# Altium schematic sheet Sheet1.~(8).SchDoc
size A
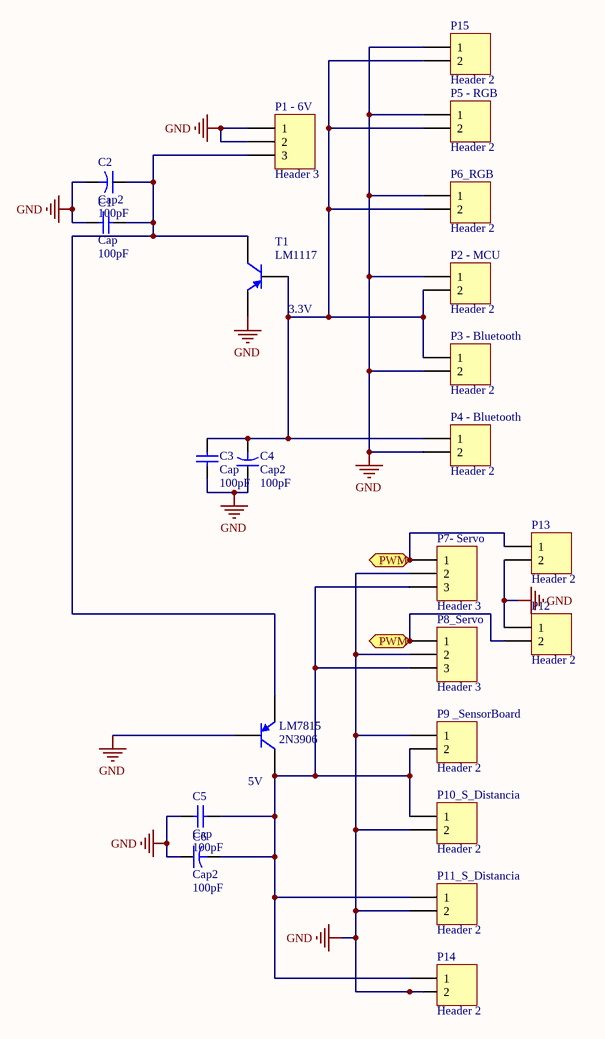
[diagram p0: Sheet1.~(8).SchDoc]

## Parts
C1  Cap  value 100pF  [RAD-0.2]
C2  Cap2  value 100pF  [CAPR5-4X5]
C3  Cap  value 100pF  [RAD-0.2]
C4  Cap2  value 100pF  [CAPR5-4X5]
C5  Cap  value 100pF  [RAD-0.2]
C6  Cap2  value 100pF  [CAPR5-4X5]
LM7815  2N3906  [TO-220-AB]
P1_-_6V  Header 3  [HDR1X3]
P2_-_MCU  Header 2  [HDR1X2]
P3_-_Bluetooth  Header 2  [HDR1X2]
P4_-_Bluetooth  Header 2  [HDR1X2]
P5_-_RGB  Header 2  [HDR1X2]
P6_RGB  Header 2  [HDR1X2]
P7-_Servo  Header 3  [HDR1X3]
P8_Servo  Header 3  [HDR1X3]
P9__SensorBoard  Header 2  [HDR1X2]
P10_S_Distancia  Header 2  [HDR1X2]
P11_S_Distancia  Header 2  [HDR1X2]
P12  Header 2  [HDR1X2]
P13  Header 2  [HDR1X2]
P14  Header 2  [HDR1X2]
P15  Header 2  [HDR1X2]
T1  LM1117  [TO-220-AB]

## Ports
PWM

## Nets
GND: C1.1 C2.2 C3.2 C4.1 C5.2 C6.1 LM7815.3(C) P1_-_6V.1 P1_-_6V.2 P2_-_MCU.1 P3_-_Bluetooth.2 P4_-_Bluetooth.2 P5_-_RGB.1 P6_RGB.1 P7-_Servo.2 P8_Servo.2 P9__SensorBoard.1 P10_S_Distancia.2 P11_S_Distancia.2 P12.1 P13.2 P14.2 P15.1 T1.1(E)
PWM: P7-_Servo.1 P8_Servo.1 P12.2 P13.1 ; port PWM
NetC1_2: C1.2 C2.1 LM7815.1(E) P1_-_6V.3 T1.2(B)
NetC3_1: C3.1 C4.2 P2_-_MCU.2 P3_-_Bluetooth.1 P4_-_Bluetooth.1 P5_-_RGB.2 P6_RGB.2 P15.2 T1.3(C)
NetC5_1: C5.1 C6.2 LM7815.2(B) P7-_Servo.3 P8_Servo.3 P9__SensorBoard.2 P10_S_Distancia.1 P11_S_Distancia.1 P14.1

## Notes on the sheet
- (near T1) 3.3V
- (near LM7815) 5V

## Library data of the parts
C1 C3 C5 = Cap: Capacitor
C2 C4 C6 = Cap2: Capacitor
LM7815 T1 = 2N3906: PNP General Purpose Amplifier
P1_-_6V P7-_Servo P8_Servo = Header 3: Header, 3-Pin
P2_-_MCU P3_-_Bluetooth P4_-_Bluetooth P5_-_RGB P6_RGB P9__SensorBoard P10_S_Distancia P11_S_Distancia P12-P15 = Header 2: Header, 2-Pin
